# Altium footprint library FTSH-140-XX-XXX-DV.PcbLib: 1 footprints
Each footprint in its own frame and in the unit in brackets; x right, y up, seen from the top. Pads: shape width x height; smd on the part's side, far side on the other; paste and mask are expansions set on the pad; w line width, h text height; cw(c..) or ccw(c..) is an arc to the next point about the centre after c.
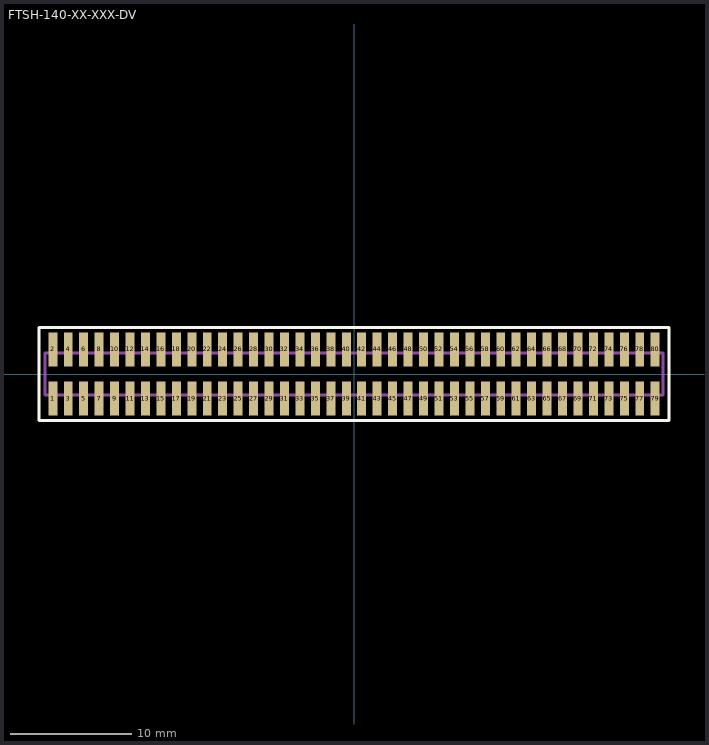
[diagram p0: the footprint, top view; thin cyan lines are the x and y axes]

## FTSH-140-XX-XXX-DV [mil]
pads (80):
  rect 29x110 smd mask+2: 1(-975,-80) 2(-975,80) 3(-925,-80) 4(-925,80) 5(-875,-80) 6(-875,80) 7(-825,-80) 8(-825,80) 9(-775,-80) 10(-775,80) 11(-725,-80) 12(-725,80) 13(-675,-80) 14(-675,80) 15(-625,-80) 16(-625,80) 17(-575,-80) 18(-575,80) 19(-525,-80) 20(-525,80) 21(-475,-80) 22(-475,80) 23(-425,-80) 24(-425,80) 25(-375,-80) 26(-375,80) 27(-325,-80) 28(-325,80) 29(-275,-80) 30(-275,80) 31(-225,-80) 32(-225,80) 33(-175,-80) 34(-175,80) 35(-125,-80) 36(-125,80) 37(-75,-80) 38(-75,80) 39(-25,-80) 40(-25,80) 41(25,-80) 42(25,80) 43(75,-80) 44(75,80) 45(125,-80) 46(125,80) 47(175,-80) 48(175,80) 49(225,-80) 50(225,80) 51(275,-80) 52(275,80) 53(325,-80) 54(325,80) 55(375,-80) 56(375,80) 57(425,-80) 58(425,80) 59(475,-80) 60(475,80) 61(525,-80) 62(525,80) 63(575,-80) 64(575,80) 65(625,-80) 66(625,80) 67(675,-80) 68(675,80) 69(725,-80) 70(725,80) 71(775,-80) 72(775,80) 73(825,-80) 74(825,80) 75(875,-80) 76(875,80) 77(925,-80) 78(925,80) 79(975,-80) 80(975,80)
Top Overlay:
  lines w10: -1020,-150 -1020,150 1020,150 1020,-150 -1020,-150
Mechanical 1:
  lines w10: -1000,-67.5 -1000,67.5 1000,67.5 1000,-67.5 -1000,-67.5
  text "J1" at -17.57,-18 h30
